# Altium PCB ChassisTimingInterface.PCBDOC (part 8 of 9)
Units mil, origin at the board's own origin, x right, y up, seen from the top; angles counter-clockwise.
Board outline 7007.87 x 4368.85 mil, 10 copper layers (Top Layer, Int1 (GND), Int2 (Sign), Int3 (Sign), Int4 (PWR), Int5 (GND), Int6 (Sign), Int7 (Sign), Int8 (GND), Bottom Layer), stack 54.89 mil thick; 537 components, 525 nets, 2288 pads, 1306 vias.
Unrouted connection lines stored in the file: 373.
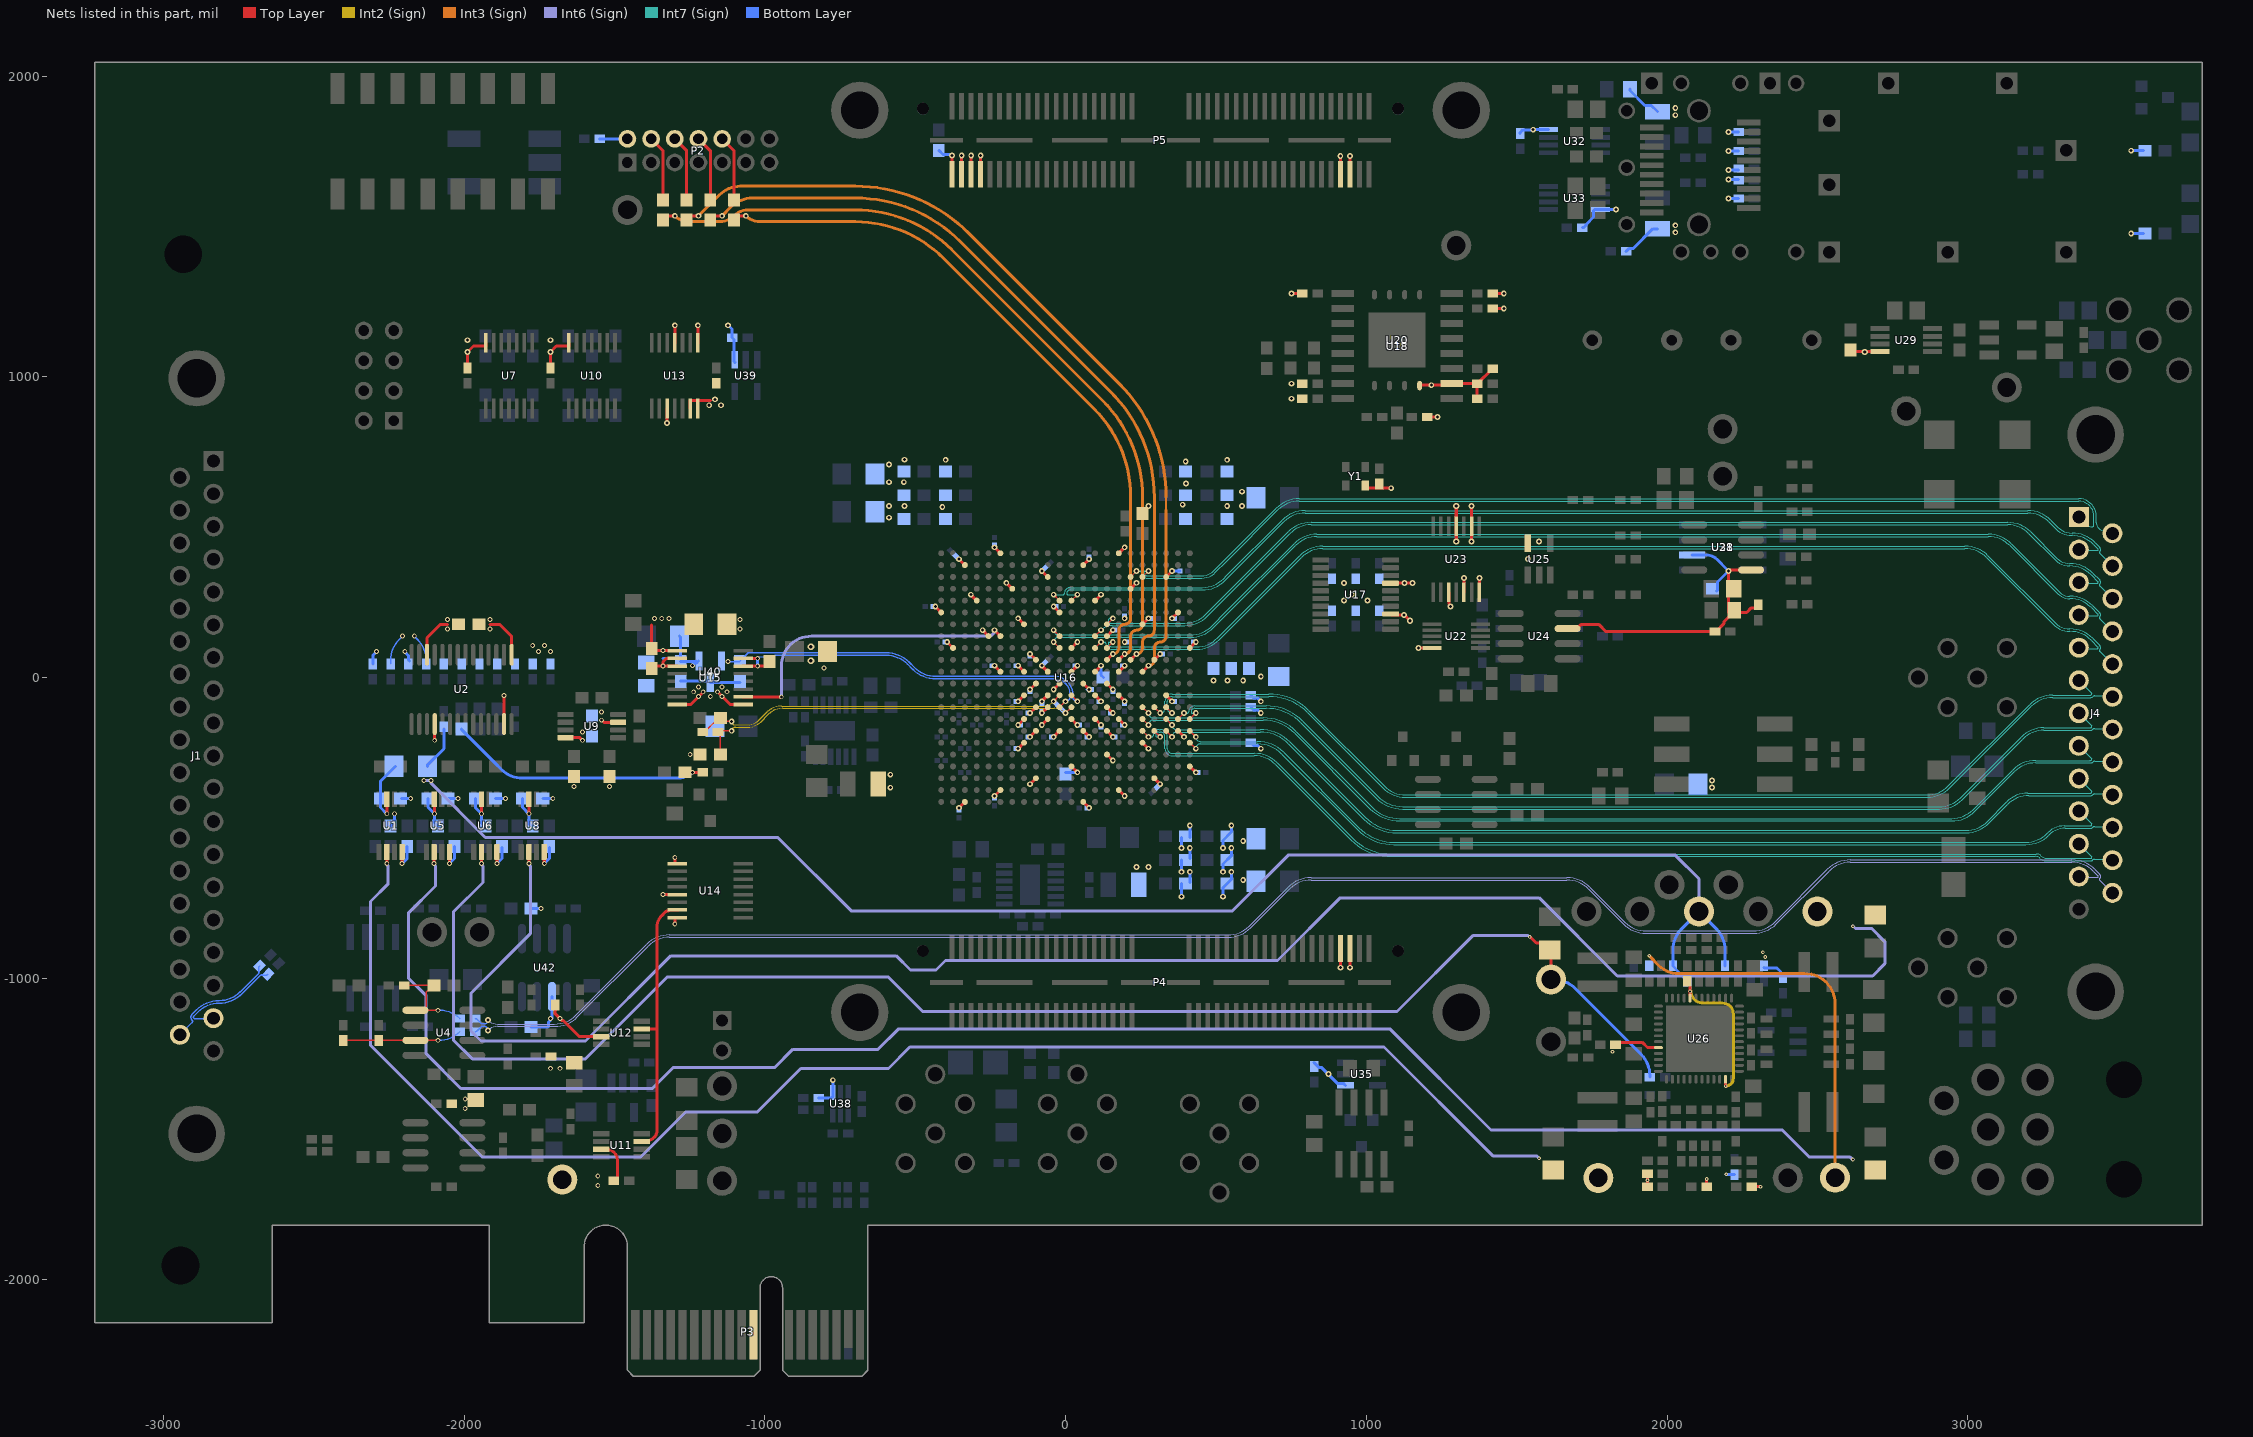
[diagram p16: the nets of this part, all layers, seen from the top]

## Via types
v1: diameter 19, hole 10, Top Layer to Bottom Layer, tented both sides, 667 vias
v2: diameter 20, hole 10, Top Layer to Bottom Layer, tented both sides, 248 vias
v3: diameter 16, hole 10, Top Layer to Bottom Layer, tented both sides, 191 vias
v4: diameter 12, hole 6, Top Layer to Bottom Layer, tented both sides, 85 vias
v5: diameter 19.68, hole 10, Top Layer to Bottom Layer, tented both sides, 50 vias
v6: diameter 17.72, hole 10, Top Layer to Bottom Layer, tented both sides, 19 vias
v7: diameter 19, hole 10, Top Layer to Bottom Layer, 15 vias
v8: diameter 23.62, hole 10, Top Layer to Bottom Layer, tented both sides, 14 vias
v9: diameter 20, hole 10, Top Layer to Bottom Layer, 11 vias
v10: diameter 16, hole 10, Top Layer to Bottom Layer, 3 vias
v11: diameter 22, hole 12, Top Layer to Bottom Layer, tented both sides, 2 vias
v12: diameter 19.02, hole 10, Top Layer to Bottom Layer, tented both sides, 1 vias

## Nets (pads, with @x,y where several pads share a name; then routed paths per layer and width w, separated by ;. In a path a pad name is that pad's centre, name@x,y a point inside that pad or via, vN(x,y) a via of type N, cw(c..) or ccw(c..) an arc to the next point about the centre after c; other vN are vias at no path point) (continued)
SQSPI.XMUX3: U15.10 U16.F15 | length 1033.6
  Top Layer w10: U15.10@-1071.85,-63.98 v3(-944.88,-63.98) ; v1(-236.22,157.48) U16.F15@-216.54,137.8
  Int6 (Sign) w10: v3(-944.88,-63.98) -944.88,37.8 cw(c-844.88,37.8) -844.88,137.8 -536.42,137.8 -255.91,137.8 ccw(c-255.91,157.48) v1(-236.22,157.48)
SYNC: U11.7 U12.7 U14.15 | length 900.2
  Top Layer w9.5: -1358.27,-1475.38 -1358.27,-1461.62 ; -1358.27,-1321.84 -1358.27,-1308.08
  Top Layer w10: U11.7@-1409.45,-1542.32 -1400.4,-1542.32 ccw(c-1400.4,-1496.21) -1381.66,-1538.34 ccw(c-1400.4,-1496.21) -1367.82,-1528.84 ; U12.7@-1409.45,-1168.31 -1358.27,-1168.31 ; -1367.79,-1528.82 ccw(c-1390.79,-1505.82) -1358.27,-1505.82 -1358.27,-1475.38 ; -1358.27,-1461.62 -1358.27,-1321.84 ; -1358.27,-1308.08 -1358.27,-1168.31 ; U14.15@-1290.35,-772.64 -1291.26,-773.54 -1317.83,-773.54 -1320.33,-776.04 -1323.25,-776.04 ccw(c-1323.25,-785.63) -1323.72,-776.05 ccw(c-1323.25,-785.63) -1330.02,-778.84 -1342.75,-791.57 ccw(c-1305.29,-829.03) -1358.27,-829.03 -1358.27,-1168.31
T1_11.T1_N: J4.14 U16.V20 | length 3444.8
  Top Layer w5: U16.V20@255.91,334.65 v1(275.59,354.33)
  Int7 (Sign) w3: v1(275.59,354.33) 263.84,354.33 ccw(c263.84,350.39) 259.91,350.39 ccw(c271.72,350.39) 271.72,338.58 452.76,338.58 ccw(c452.76,395.61) 493.08,355.29 536.42,398.62 700.85,563.05 cw(c777.05,486.85) 777.05,594.61 3369.29,594.61 cw(c3369.29,536.61) 3427.29,536.61 3427.29,515.43 ccw(c3454.68,515.43) 3435.31,496.06 ccw(c3454.68,515.43) 3454.68,488.04 3461.06,488.04 cw(c3461.06,459.71) J4.14@3481.1,479.74
T1_11.T1_P: J4.1 U16.U20 | length 3456.6
  Top Layer w5: U16.U20@216.54,334.65 v1(236.22,354.33)
  Int7 (Sign) w3: v1(236.22,354.33) 247.97,354.33 cw(c247.97,350.39) 251.91,350.39 ccw(c271.72,350.39) 271.72,330.58 452.86,330.58 ccw(c452.86,395.35) 498.66,349.55 536.42,387.31 706.43,557.32 cw(c777.14,486.61) 777.14,586.61 3369.29,586.61 cw(c3369.29,536.61) 3419.29,536.61 3419.29,533.3 3419.29,514.74 3419.29,505.33 ; J4.1@3369.29,534.09 3395.23,508.15 ccw(c3409.3,522.22) 3409.3,502.33 3416.29,502.33 ccw(c3416.29,505.33) 3418.42,503.21 ccw(c3416.29,505.33) 3419.29,505.33 ; 3419.29,514.69 3419.29,505.33
T1_11.T2_N: J4.15 U16.L18 | length 3736.8
  Top Layer w5: v1(-39.37,275.59) U16.L18@-19.69,255.91
  Int7 (Sign) w3: v1(-39.37,275.59) -7.94,275.59 ccw(c-7.94,279.53) -4,279.53 cw(c15.81,279.53) 15.81,299.34 454.77,299.34 ccw(c454.77,399.34) 525.48,328.63 536.42,339.57 720.53,523.68 cw(c796.73,447.48) 796.73,555.24 3199.33,555.24 cw(c3199.33,447.48) 3275.53,523.68 3298.95,500.26 ccw(c3346.8,548.11) 3346.8,480.44 cw(c3346.8,372.53) 3423.11,448.83 3438.59,433.35 cw(c3430.9,425.65) 3441.78,425.65 ; 3441.78,425.61 cw(c3430.78,425.61) 3438.56,417.83 ccw(c3440.68,415.71) 3437.68,415.71 ccw(c3440.68,415.71) 3438.56,413.58 J4.15@3481.1,371.04
T1_11.T2_P: J4.2 U16.M18 | length 3705.1
  Top Layer w5: U16.M18@19.69,255.91 v1(39.37,275.59)
  Int7 (Sign) w3: v1(39.37,275.59) 7.94,275.59 cw(c7.94,279.53) 4,279.53 cw(c15.81,279.53) 15.81,291.34 454.81,291.34 ccw(c454.81,399.24) 531.11,322.94 536.42,328.25 726.12,517.95 cw(c796.83,447.24) 796.83,547.24 3199.23,547.24 cw(c3199.23,447.24) 3269.94,517.95 3293.34,494.56 ccw(c3346.74,547.95) 3346.74,472.44 cw(c3346.77,372.44) 3417.48,443.15 3432.9,427.73 cw(c3430.78,425.61) 3433.78,425.61 cw(c3430.78,425.61) 3432.9,423.48 cw(c3430.78,425.61) 3430.78,422.61 3376.02,422.61 cw(c3376.02,432.13) J4.2@3369.29,425.39
T1_11.T3_N: J4.16 U16.R16 | length 3628.5
  Top Layer w5: U16.R16@137.8,177.17 v1(157.48,196.85)
  Int7 (Sign) w3: v1(157.48,196.85) 149.61,196.85 ccw(c149.61,188.98) 141.73,188.98 ccw(c149.54,188.98) 149.54,181.17 395.65,181.17 ccw(c395.65,281.17) 466.36,210.45 536.42,280.51 740.22,484.31 cw(c816.42,408.11) 816.42,515.87 3132.67,515.87 cw(c3132.67,408.11) 3208.86,484.31 3296.19,396.98 ccw(c3339.5,440.29) 3339.5,379.04 cw(c3339.5,271.13) 3415.81,347.44 3438.59,324.65 cw(c3430.9,316.95) 3441.78,316.95 ; 3441.78,316.9 cw(c3430.78,316.9) 3438.56,309.13 ccw(c3440.68,307) 3437.68,307 ccw(c3440.68,307) 3438.56,304.88 J4.16@3481.1,262.34
T1_11.T3_P: J4.3 U16.P15 | length 3612.5
  Top Layer w5: U16.P15@98.43,137.8 v1(118.11,157.48)
  Int7 (Sign) w3: v1(118.11,157.48) cw(c155.98,119.61) 155.98,173.17 395.69,173.17 ccw(c395.69,281.07) 471.99,204.77 536.42,269.2 745.8,478.58 cw(c816.51,407.87) 816.51,507.87 3132.57,507.87 cw(c3132.57,407.87) 3203.28,478.58 3290.58,391.28 ccw(c3339.43,440.13) 3339.43,371.04 cw(c3339.47,271.04) 3410.18,341.75 3432.9,319.03 cw(c3430.78,316.9) 3433.78,316.9 cw(c3430.78,316.9) 3432.9,314.78 cw(c3430.78,316.9) 3430.78,313.9 3376.02,313.9 cw(c3376.02,323.43) J4.3@3369.29,316.69
T1_11.T4_N: J4.17 U16.L15 | length 3823.1
  Top Layer w5: v1(-39.37,157.48) U16.L15@-19.69,137.8
  Int7 (Sign) w3: v1(-39.37,157.48) ccw(c-23.69,157.48) -23.69,141.8 415.34,141.8 ccw(c415.34,241.8) 486.05,171.09 536.42,221.46 759.9,444.94 cw(c836.1,368.74) 836.1,476.5 3068.68,476.5 cw(c3068.68,368.56) 3145.01,444.89 3305.45,284.45 ccw(c3339.5,318.5) 3339.5,270.34 cw(c3339.5,162.43) 3415.81,238.73 3438.59,215.95 cw(c3430.9,208.25) 3441.78,208.25 ; 3441.78,208.2 cw(c3430.78,208.2) 3438.56,200.43 ccw(c3440.68,198.3) 3437.68,198.3 ccw(c3440.68,198.3) 3438.56,196.18 J4.17@3481.1,153.64
T1_11.T4_P: J4.4 U16.L14 | length 3804
  Top Layer w5: v1(-39.37,118.11) U16.L14@-19.69,98.43
  Int7 (Sign) w3: v1(-39.37,118.11) cw(c-23.69,118.11) -23.69,133.8 415.38,133.8 ccw(c415.38,241.7) 491.67,165.4 536.42,210.14 765.49,439.21 cw(c836.2,368.5) 836.2,468.5 3068.66,468.5 cw(c3068.66,368.5) 3139.37,439.21 3299.82,278.76 ccw(c3339.46,318.4) 3339.46,262.34 cw(c3339.47,162.34) 3410.18,233.05 3432.9,210.32 cw(c3430.78,208.2) 3433.78,208.2 cw(c3430.78,208.2) 3432.9,206.08 cw(c3430.78,208.2) 3430.78,205.2 3376.02,205.2 cw(c3376.02,214.72) J4.4@3369.29,207.99
T1_11.T5_N: J4.18 U16.R14 | length 3685.5
  Top Layer w5: U16.R14@137.8,98.43 v1(157.48,118.11)
  Int7 (Sign) w3: v1(157.48,118.11) 145.73,118.11 ccw(c145.73,114.17) 141.8,114.17 ccw(c153.61,114.17) 153.61,102.36 434.96,102.36 ccw(c434.96,202.36) 505.67,131.65 536.42,162.4 779.59,405.57 cw(c855.79,329.37) 855.79,437.13 2990.75,437.13 cw(c2990.75,329.19) 3067.07,405.52 3290.76,181.83 ccw(c3339.5,230.57) 3339.5,161.64 cw(c3339.5,53.73) 3415.81,130.03 3438.59,107.25 cw(c3430.9,99.55) 3441.78,99.55 ; 3441.78,99.5 cw(c3430.78,99.5) 3438.56,91.72 ccw(c3440.68,89.6) 3437.68,89.6 ccw(c3440.68,89.6) 3438.56,87.48 J4.18@3481.1,44.94
T1_11.T5_P: J4.5 U16.P14 | length 3679
  Top Layer w5: U16.P14@98.43,98.43 v1(118.11,118.11)
  Int7 (Sign) w3: v1(118.11,118.11) 129.86,118.11 cw(c129.86,114.17) 133.8,114.17 ccw(c153.61,114.17) 153.61,94.36 435,94.36 ccw(c435,202.26) 511.29,125.97 536.42,151.09 785.17,399.84 cw(c855.88,329.13) 855.88,429.13 2990.72,429.13 cw(c2990.72,329.13) 3061.43,399.84 3285.13,176.14 ccw(c3339.46,230.47) 3339.46,153.64 cw(c3339.47,53.64) 3410.18,124.35 3432.9,101.62 cw(c3430.78,99.5) 3433.78,99.5 cw(c3430.78,99.5) 3432.9,97.38 cw(c3430.78,99.5) 3430.78,96.5 3376.02,96.5 cw(c3376.02,106.02) J4.5@3369.29,99.29
T1_11.T6_N: J4.19 U16.Y9 | length 3484.4
  Top Layer w5: U16.Y9@334.65,-98.43 v1(354.33,-118.11)
  Int7 (Sign) w3: v1(354.33,-118.11) cw(c354.33,-102.43) 338.65,-102.43 338.65,-78.68 cw(c354.33,-78.68) 354.33,-62.99 536.42,-62.99 676.45,-62.99 cw(c676.45,-242.99) 803.73,-115.71 1054.15,-366.13 ccw(c1130.51,-289.76) 1130.51,-397.76 2864.63,-397.76 ccw(c2864.63,-289.86) 2940.93,-366.16 3211.48,-95.6 cw(c3282.19,-166.31) 3282.19,-66.31 3409.25,-66.31 ccw(c3409.25,-57.19) 3415.7,-63.64 cw(c3422.15,-70.09) 3422.15,-60.97 3474.37,-60.97 cw(c3474.37,-70.49) J4.19@3481.1,-63.76
T1_11.T6_P: J4.6 U16.W9 | length 3491
  Top Layer w5: U16.W9@295.28,-98.43 v1(314.96,-118.11)
  Int7 (Sign) w3: v1(314.96,-118.11) ccw(c314.96,-102.43) 330.65,-102.43 330.65,-78.68 cw(c354.33,-78.68) 354.33,-54.99 536.42,-54.99 676.45,-54.99 cw(c676.45,-242.99) 809.39,-110.06 1059.8,-360.47 ccw(c1130.51,-289.76) 1130.51,-389.76 2864.59,-389.76 ccw(c2864.59,-289.76) 2935.3,-360.47 3205.86,-89.92 ; 3205.86,-89.92 cw(c3282.15,-166.21) 3282.15,-58.31 3406.71,-58.31 ccw(c3406.71,-51.07) 3411.83,-56.19 ccw(c3409.71,-54.07) 3412.71,-54.07 ccw(c3409.71,-54.07) 3411.83,-51.95 J4.6@3369.29,-9.41
T1_11.T7_N: J4.20 U16.AB8 | length 3344.3
  Top Layer w5: U16.AB8@413.39,-137.8 v1(433.07,-118.11)
  Int7 (Sign) w3: v1(433.07,-118.11) 421.32,-118.11 cw(c421.32,-114.17) 417.39,-114.17 cw(c429.2,-114.17) 429.2,-102.36 536.42,-102.36 666.77,-102.36 cw(c666.77,-266.36) 782.73,-150.4 1033.15,-400.81 ccw(c1120.83,-313.13) 1120.83,-437.13 2905.22,-437.13 ccw(c2905.22,-329.23) 2981.52,-405.53 3182.75,-204.3 cw(c3253.46,-275.01) 3253.46,-175.01 3409.25,-175.01 ccw(c3409.25,-165.89) 3415.7,-172.34 cw(c3422.15,-178.79) 3422.15,-169.67 3474.37,-169.67 cw(c3474.37,-179.19) J4.20@3481.1,-172.46
T1_11.T7_P: J4.7 U16.AA8 | length 3350.9
  Top Layer w5: U16.AA8@374.02,-137.8 v1(393.7,-118.11)
  Int7 (Sign) w3: v1(393.7,-118.11) 405.45,-118.11 ccw(c405.45,-114.17) 409.39,-114.17 cw(c429.2,-114.17) 429.2,-94.36 536.42,-94.36 666.77,-94.36 cw(c666.77,-266.36) 788.39,-144.74 1038.81,-395.16 ccw(c1120.83,-313.13) 1120.83,-429.13 2905.18,-429.13 ccw(c2905.18,-329.13) 2975.89,-399.84 3177.12,-198.62 cw(c3253.42,-274.92) 3253.42,-167.01 3406.71,-167.01 ccw(c3406.71,-159.77) 3411.83,-164.89 ccw(c3409.71,-162.77) 3412.71,-162.77 ccw(c3409.71,-162.77) 3411.83,-160.65 J4.7@3369.29,-118.11
T1_11.T8_N: J4.21 U16.V8 | length 3441.7
  Top Layer w5: U16.V8@255.91,-137.8 v1(275.59,-157.48)
  Int7 (Sign) w3: v1(275.59,-157.48) cw(c291.28,-157.48) 291.28,-141.8 536.42,-141.8 657.06,-141.8 cw(c657.06,-289.8) 761.71,-185.14 1012.13,-435.56 ccw(c1111.13,-336.57) 1111.13,-476.57 2946.99,-476.57 ccw(c2946.99,-368.67) 3023.28,-444.96 3155.24,-313.01 cw(c3225.95,-383.72) 3225.95,-283.72 3409.25,-283.72 ccw(c3409.25,-274.59) 3415.7,-281.04 cw(c3422.15,-287.49) 3422.15,-278.37 3474.37,-278.37 cw(c3474.37,-287.89) J4.21@3481.1,-281.16
T1_11.T8_P: J4.8 U16.V9 | length 3435.7
  Top Layer w5: U16.V9@255.91,-98.43 v1(275.59,-118.11)
  Int7 (Sign) w3: v1(275.59,-118.11) ccw(c291.28,-118.11) 291.28,-133.8 536.42,-133.8 657.06,-133.8 cw(c657.06,-289.8) 767.37,-179.49 1017.79,-429.91 ccw(c1111.13,-336.57) 1111.13,-468.57 2946.95,-468.57 ccw(c2946.95,-368.57) 3017.66,-439.28 3149.62,-307.32 cw(c3225.91,-383.62) 3225.91,-275.72 3406.71,-275.72 ccw(c3406.71,-268.47) 3411.83,-273.59 ccw(c3409.71,-271.47) 3412.71,-271.47 ccw(c3409.71,-271.47) 3411.83,-269.35 J4.8@3369.29,-226.81
T1_11.T9_N: J4.22 U16.Y7 | length 3334.2
  Top Layer w5: U16.Y7@334.65,-177.17 v1(354.33,-196.85)
  Int7 (Sign) w3: v1(354.33,-196.85) cw(c370.02,-196.85) 370.02,-181.17 536.42,-181.17 647.38,-181.17 cw(c647.38,-313.17) 740.72,-219.83 991.14,-470.25 ccw(c1101.45,-359.94) 1101.45,-515.94 2993.99,-515.94 ccw(c2993.99,-408.04) 3070.29,-484.33 3132.92,-421.71 cw(c3203.63,-492.42) 3203.63,-392.42 3409.25,-392.42 ccw(c3409.25,-383.3) 3415.7,-389.74 cw(c3422.15,-396.19) 3422.15,-387.07 3474.37,-387.07 cw(c3474.37,-396.6) J4.22@3481.1,-389.86
T1_11.T9_P: J4.9 U16.Y8 | length 3328.6
  Top Layer w5: U16.Y8@334.65,-137.8 v1(354.33,-157.48)
  Int7 (Sign) w3: v1(354.33,-157.48) ccw(c370.02,-157.48) 370.02,-173.17 536.42,-173.17 647.38,-173.17 cw(c647.38,-313.17) 746.38,-214.17 996.8,-464.59 ccw(c1101.45,-359.94) 1101.45,-507.94 2993.95,-507.94 ccw(c2993.95,-407.94) 3064.66,-478.65 3129.92,-413.39 cw(c3199.86,-483.32) 3199.86,-384.42 3406.71,-384.42 ccw(c3406.71,-377.17) 3411.83,-382.3 ccw(c3409.71,-380.17) 3412.71,-380.17 ccw(c3409.71,-380.17) 3411.83,-378.05 J4.9@3369.29,-335.51
T1_11.T10_N: J4.23 U16.AB6 | length 3227.8
  Top Layer w5: U16.AB6@413.39,-216.54 v1(433.07,-236.22)
  Int7 (Sign) w3: v1(433.07,-236.22) cw(c448.76,-236.22) 448.76,-220.54 536.42,-220.54 637.7,-220.54 cw(c637.7,-336.54) 719.73,-254.51 970.14,-504.93 ccw(c1091.77,-383.31) 1091.77,-555.31 3193.58,-555.31 ccw(c3193.58,-447.41) 3269.87,-523.7 cw(c3324.4,-578.23) 3324.4,-501.12 3409.25,-501.12 ccw(c3409.25,-492) 3415.7,-498.45 cw(c3422.15,-504.9) 3422.15,-495.77 3474.37,-495.77 cw(c3474.37,-505.3) J4.23@3481.1,-498.56
T1_11.T10_P: J4.10 U16.AB7 | length 3222.1
  Top Layer w5: U16.AB7@413.39,-177.17 v1(433.07,-196.85)
  Int7 (Sign) w3: v1(433.07,-196.85) ccw(c448.76,-196.85) 448.76,-212.54 536.42,-212.54 637.7,-212.54 cw(c637.7,-336.54) 725.38,-248.86 975.8,-499.27 ccw(c1091.77,-383.31) 1091.77,-547.31 3193.53,-547.31 ccw(c3193.53,-447.31) 3264.24,-518.02 3266.33,-515.94 cw(c3321.42,-571.03) 3321.42,-493.12 3406.71,-493.12 ccw(c3406.71,-485.87) 3411.83,-491 ccw(c3409.71,-488.87) 3412.71,-488.87 ccw(c3409.71,-488.87) 3411.83,-486.75 J4.10@3369.29,-444.21
T1_11.T11_N: J4.24 U16.W7 | length 3428.1
  Top Layer w5: U16.W7@295.28,-177.17 v1(314.96,-196.85)
  Int7 (Sign) w3: v1(314.96,-196.85) 303.21,-196.85 cw(c303.21,-192.91) 299.28,-192.91 cw(c311.09,-192.91) 311.09,-181.1 314.96,-181.1 cw(c314.96,-196.85) 330.71,-196.85 330.71,-236.35 ccw(c354.33,-236.35) 354.33,-259.97 536.42,-259.97 628,-259.97 cw(c628,-359.97) 698.71,-289.26 949.12,-539.68 ccw(c1082.06,-406.74) 1082.06,-594.74 3224.9,-594.74 cw(c3224.9,-618.36) 3241.6,-601.66 ccw(c3258.3,-584.96) 3258.3,-608.58 3411.37,-608.58 ccw(c3411.37,-601.58) 3416.32,-606.53 cw(c3421.27,-611.47) 3421.27,-604.47 3474.37,-604.47 cw(c3474.37,-614) J4.24@3481.1,-607.26
T1_11.T11_P: J4.11 U16.V7 | length 3434.7
  Top Layer w5: U16.V7@255.91,-177.17 v1(275.59,-196.85)
  Int7 (Sign) w3: v1(275.59,-196.85) 287.34,-196.85 ccw(c287.34,-192.91) 291.28,-192.91 cw(c311.09,-192.91) 311.09,-173.1 314.96,-173.1 cw(c314.96,-196.85) 338.71,-196.85 338.71,-236.35 ccw(c354.33,-236.35) 354.33,-251.97 536.42,-251.97 628,-251.97 cw(c628,-359.97) 704.36,-283.6 954.78,-534.02 ccw(c1082.06,-406.74) 1082.06,-586.74 3228.21,-586.74 cw(c3228.21,-610.36) 3244.91,-593.66 ccw(c3261.61,-576.96) 3261.61,-600.58 3409.71,-600.58 ccw(c3409.71,-597.58) 3411.83,-599.7 ccw(c3409.71,-597.58) 3412.71,-597.58 ccw(c3409.71,-597.58) 3411.83,-595.45 J4.11@3369.29,-552.91
TCK_FPGA: R22.2 U16.V12 | length 2769.5
  Top Layer w10: R22.2@-1259.84,1529.53 -1253.94,1535.43 v1(-1220.47,1535.43) ; U16.V12@255.91,19.69 v1(275.59,39.37)
  Int3 (Sign) w6.5: 334.65,557.93 334.65,600.32
  Int3 (Sign) w10: v1(-1220.47,1535.43) -1151.34,1604.57 cw(c-1080.63,1533.86) -1080.77,1633.86 cw(c-1080.63,1533.86) -1080.63,1633.86 ; -1082.68,1633.86 -698.89,1633.86 cw(c-698.89,1100.81) -321.97,1477.73 178.52,977.24 cw(c-198.4,600.32) 334.65,600.32 ; v1(275.59,39.37) ccw(c275.59,59.06) 295.28,59.06 295.28,98.43 cw(c314.96,98.43) 314.96,118.11 ccw(c314.96,137.8) 334.65,137.8 334.65,517.96 334.65,557.93
TCK_JTAG: P2.6 R22.1 | length 226.9
  Top Layer w10: P2.6@-1299.21,1791.34 -1259.84,1751.97 R22.1@-1259.84,1580.71
TDI_FPGA: R27.2 U16.R13 | length 2353.9
  Top Layer w10: R27.2@-1102.36,1529.53 -1096.46,1535.43 v1(-1062.99,1535.43) ; U16.R13@137.8,59.06 v1(157.48,78.74)
  Int3 (Sign) w10: v1(-1062.99,1535.43) ccw(c-1015.47,1582.96) -1015.47,1515.75 -698.89,1515.75 cw(c-698.89,1100.8) -405.48,1394.21 95,893.73 cw(c-198.41,600.32) 216.54,600.32 216.54,517.96 216.54,196.85 cw(c196.85,196.85) 196.85,177.17 ccw(c196.85,157.48) 177.17,157.48 177.17,98.43 cw(c157.48,98.43) v1(157.48,78.74)
TDI_JTAG: P2.10 R27.1 | length 226.9
  Top Layer w10: P2.10@-1141.73,1791.34 -1102.36,1751.97 R27.1@-1102.36,1580.71
TDO_FPGA: R26.2 U16.U13 | length 2571.2
  Top Layer w10: R26.2@-1181.1,1529.53 -1175.2,1535.43 v1(-1141.73,1535.43) ; U16.U13@216.54,59.06 v1(236.22,78.74)
  Int3 (Sign) w10: v1(-1141.73,1535.43) -1111.97,1565.2 cw(c-1041.26,1494.49) -1041.4,1594.49 cw(c-1041.26,1494.49) -1041.26,1594.49 -964.57,1594.49 -698.89,1594.49 cw(c-698.89,1100.81) -349.81,1449.89 150.68,949.41 cw(c-198.41,600.32) 295.28,600.32 295.28,517.96 295.28,157.48 cw(c275.59,157.48) 275.59,137.8 ccw(c275.59,118.11) 255.91,118.11 255.91,98.43 cw(c236.22,98.43) v1(236.22,78.74)
TDO_JTAG: P2.8 R26.1 | length 226.9
  Top Layer w10: P2.8@-1220.47,1791.34 -1181.1,1751.97 R26.1@-1181.1,1580.71
TMS_FPGA: R20.2 U16.T13 | length 2662.5
  Top Layer w10: R20.2@-1338.58,1529.53 -1332.68,1535.43 v1(-1299.21,1535.43) ; U16.T13@177.17,59.06 v1(196.85,78.74)
  Int3 (Sign) w10: v1(-1299.21,1535.43) ccw(c-1251.69,1582.96) -1251.69,1515.75 -1149.89,1515.75 ccw(c-1149.89,1582.96) -1102.36,1535.43 cw(c-1054.84,1487.91) -1054.84,1555.12 -698.89,1555.12 cw(c-698.89,1100.81) -377.65,1422.05 122.84,921.57 cw(c-198.41,600.32) 255.91,600.32 255.91,517.96 255.91,177.17 cw(c236.22,177.17) 236.22,157.48 ccw(c236.22,137.8) 216.54,137.8 216.54,98.43 cw(c196.85,98.43) v1(196.85,78.74)
TMS_JTAG: P2.4 R20.1 | length 226.9
  Top Layer w10: P2.4@-1377.95,1791.34 -1338.58,1751.97 R20.1@-1338.58,1580.71
VCC: C6.1 C12.1 C23.1 C68.1 C87.2 C88.2 C90.2 C92.2 C94.2 C95.2 C96.2 C97.2 C98.2 C99.2 C100.2 C184.2 C200.2 FR1.1 FR3.2 L6.2 L7.2 P5.1 P5.3 P5.5 P5.7 R49.2 R103.2 R104.2 R108.2 R109.2 R111.2 R112.2 R169.1 TP12.1 U1.2 U7.14 U10.14 U13.1 U13.4 U13.10 U13.13 U13.14 U14.9 U14.13 U14.16 U17.13 U17.17 U23.2 U23.4 U23.10 U23.12 U23.14 U25.5 U29.8 U32.8 U33.8 U35.1 U39.1 | length 7577.4
  Top Layer w10: v3(-2256.89,-618.11) U1.2@-2256.89,-579.72 ; C6.1@-1988.19,1042.32 v1(-1988.19,1082.68) -1968.5,1102.36 -1928.07,1102.36 -1927.17,1103.27 U7.14@-1927.17,1113.19 ; -1712.6,1047.24 v1(-1712.6,1082.68) -1692.91,1102.36 -1652.48,1102.36 -1651.57,1103.27 U10.14@-1651.57,1113.19 ; v3(-1338.58,-721.46) U14.13@-1290.35,-721.46 ; v1(-1324.8,846.46) U13.10@-1324.8,894.69 ; v3(-1299.21,-818.9) U14.16@-1299.21,-799.21 ; U14.9@-1299.21,-618.11 v3(-1299.21,-598.43) ; U13.4@-1299.21,1113.19 v1(-1299.21,1171.5) ; U13.13@-1248.03,894.69 -1248.03,920.35 -1247.13,921.26 -1181.1,921.26 ; U13.1@-1222.44,1113.19 v1(-1222.44,1171.5) ; P5.1@-377.15,1673.83 v7(-377.15,1736.22) ; P5.3@-345.67,1673.83 v1@-345.67,1736.22 ; P5.5@-314.17,1673.83 v1@-314.17,1736.22 ; P5.7@-282.67,1673.83 v1@-282.67,1736.22 ; U17.13@1080.71,211.61 1083.66,208.66 v9(1125.98,208.66) v9(1145.67,188.98) ; U17.17@1080.71,313.98 1081.69,314.96 v9(1153.54,314.96) ; U23.10@1273.62,284.45 1274.53,283.54 1274.53,243.93 1279.53,238.93 v2(1279.53,236.22) ; v2(1299.21,452.76) v2(1299.21,570.87) ; U23.12@1324.8,284.45 v2(1324.8,330.77) ; v2(1350.39,452.76) v2(1350.39,570.87) ; U23.14@1375.98,284.45 v2(1375.98,330.77) ; C68.1@2598.43,1083.66 U29.8@2708.86,1083.66 ; v2(2657.48,1082.68) cw(c2659.86,1080.3) v2@2659.86,1083.66
  Int6 (Sign) w10: v3(-2256.89,-618.11) -2255.74,-619.26 -2255.74,-623.7 -2252.22,-627.22 -2252.22,-685.65 -2310.77,-744.2 -2310.77,-1222.95 -1939.49,-1594.24 -1412.78,-1594.24 -1263.68,-1445.13 -1025.58,-1445.13 -879.91,-1299.46 -588.57,-1299.46 -517.71,-1228.6 1058.95,-1228.6 1420.65,-1590.3 1566.14,-1590.3 1574.26,-1598.43 v4(1574.8,-1598.43)
  Bottom Layer w10: R169.1@-1777.56,-767.72 v3(-1744.09,-767.72) ; v1(-1122.05,1171.5) -1109.25,1158.7 -1109.25,1130.91 -1102.43,1124.08 -1102.43,1051.24 U39.1@-1098.43,1047.24 ; C184.2@-421.26,1753.15 -407.48,1739.37 -382.74,1739.37 -379.59,1736.22 v7(-377.15,1736.22) ; C100.2@826.77,-1280.51 843.5,-1297.24 852.36,-1297.24 905.59,-1350.47 925.28,-1350.47 U35.1@931.1,-1356.3 ; C92.2@1511.81,1809.06 1511.81,1812.49 1520.59,1821.27 1554.54,1821.27 v1(1555.12,1821.85) U32.8@1606.5,1821.85 ; C90.2@1718.31,1496.06 1722.24,1496.06 1731.02,1504.84 1731.02,1506.61 1755.91,1531.51 1755.91,1552.83 1759.18,1556.1 v1(1830.71,1556.1) ; C87.2@1864.17,1417.32 1872.95,1426.1 1886.73,1426.1 1952.76,1492.13 L6.2@1968.5,1492.13 ; C88.2@1876.97,1956.69 1876.97,1951.77 1926.26,1902.48 1947.91,1902.48 L7.2@1968.5,1881.89 ; v1(2204.72,1656.3) R111.2@2238.19,1656.3 ; v1(2204.72,1687.8) R112.2@2238.19,1687.8 ; R109.2@2322.83,-964.57 2323.9,-965.63 2365.24,-965.63 2377.05,-977.44 2377.05,-985.31 2377.95,-986.22 R108.2@2385.83,-986.22 ; v1(3543.31,1476.38) R103.2@3584.65,1476.38 ; v1(3543.31,1751.97) R104.2@3584.65,1751.97
  other v1: -1185.04,905.51 -1145.67,905.51 -1165.35,925.2 -1988.19,1122.05 -1712.6,1122.05 2027.56,1480.32 2027.56,1503.94 -345.21,1736.22 -313.72,1736.22 -282.22,1736.22 2027.56,1870.08 2027.56,1893.7
  other v2: 874.02,-1318.9 2149.61,-366.14 2149.61,-342.52 925.2,255.91 1003.94,255.91 952.76,275.59 925.2,314.96 1537.4,394.69 1574.8,452.76
  other v3: -1082.68,161.42 -1082.68,192.91
  other v4: 2326.77,-929.13 2318.9,-913.39
  other v9: 1127.36,314.96
VCC1V8: C101.2 C105.2 C106.2 C113.2 C130.2 C137.2 C146.2 C151.2 C161.2 L1.2 L8.2 R48.2 R124.2 TP10.1 U6.2 U16.H12 U16.K12 U16.M12 U16.P12 U16.R11 | length 5388.3
  Top Layer w10: U6.2@-1941.93,-579.72 -1941.86,-579.8 -1941.86,-618.02 v3(-1941.78,-618.09) ; v1(-157.48,39.37) U16.H12@-137.8,19.69 ; v1(-78.74,39.37) U16.K12@-59.06,19.69 ; U16.M12@19.69,19.69 v1(39.37,39.37) ; U16.P12@98.43,19.69 v1(118.11,39.37) ; U16.R11@137.8,-19.68 v1(157.48,-39.37) ; v4(1543.31,-862.2) 1543.85,-862.2 1544.85,-863.2 1546.28,-863.2 1565.66,-882.59 1587.31,-882.59 1614.17,-909.45 TP10.1@1614.17,-1003.94
  Int6 (Sign) w10: v3(-1941.78,-618.09) -1940.63,-619.24 -1940.63,-623.32 -1937.01,-626.95 -1937.01,-681.1 -2035.43,-779.53 -2035.43,-1204.72 -1972.44,-1267.72 -1595.84,-1267.72 -1323.08,-994.96 -590.3,-994.96 -475.03,-1110.24 1102.26,-1110.24 1354.23,-858.27 1537.96,-858.27 1540.89,-861.2 1541.77,-861.2 1542.77,-862.2 v4(1543.31,-862.2)
  Bottom Layer w10: v1(118.11,39.37) 118.11,7.87 C130.2@125.98,0 ; TP10.1@1614.17,-1003.94 1623.71,-1003.94 cw(c1623.71,-1103.94) 1694.43,-1033.23 1913.62,-1252.43 cw(c1842.91,-1323.14) 1942.91,-1323.14 R124.2@1942.91,-1328.74
  other v1: 236.22,-629.92 275.59,-629.92 -582.68,-366.14 -582.68,-322.83 492.13,-9.92 538.39,-9.92 590.55,-9.92 649.61,3.94
VCC2: C5.1 C19.2 C207.1 C210.1 C212.1 C214.1 FR1.2 R16.1 R168.1 R180.1 R192.1 R198.1 U2.1 U2.18 U5.7 U6.7 U8.7 U9.7 U15.1 | length 947.8
  Top Layer w10: U5.7@-2099.41,-404.53 -2098.92,-405.02 -2098.92,-452.26 v3(-2098.43,-452.76) ; v3(-2097.44,-208.66) U2.18@-2097.44,-154.53 ; U6.7@-1941.93,-404.53 -1941.64,-404.82 v3(-1941.64,-452.76) ; -1913.39,177.17 -1881.89,177.17 -1841.54,136.81 U2.1@-1841.54,75.79 ; v3(-1784.45,-452.76) U8.7@-1784.45,-404.53 ; v3(-1543.31,-141.73) -1542.16,-142.88 -1540.19,-142.88 -1534.45,-148.62 U9.7@-1487.2,-148.62 ; -1375.98,175.2 C19.2@-1375.98,97.44 -1369.09,90.55 v3(-1338.58,90.55) ; v3@-1338.58,89.57 U15.1@-1290.35,89.57
  Bottom Layer w10: R198.1@-2244.09,-494.09 -2231.3,-481.3 v3(-2231.3,-452.76) ; C214.1@-2120.08,-401.57 -2120.08,-431.1 v3(-2098.43,-452.76) -2098.43,-482.28 R192.1@-2086.61,-494.09 ; C212.1@-1962.6,-401.57 -1962.6,-431.79 v3(-1941.64,-452.76) -1941.64,-485.53 R180.1@-1929.13,-498.03 ; C210.1@-1805.12,-401.57 -1805.12,-432.09 v3(-1784.45,-452.76) -1784.45,-485.24 R168.1@-1771.65,-498.03
  other v3: -1633.86,-362.2 -1543.31,-114.17 -1913.92,161.42 -1913.92,192.91 -1366.14,196.85 -1342.52,196.85 -1318.9,196.85
VCCINT: C102.2 C103.2 C107.2 C108.2 C109.2 C117.2 C118.2 C119.2 C131.1 C133.1 C135.1 C138.1 C139.1 C140.1 C141.2 C144.1 C145.1 C153.1 C155.2 C157.1 C158.1 C159.1 C162.1 R96.2 R126.2 TP22.1 U5.2 U16.H8 U16.H10 U16.J7 U16.J9 U16.J11 U16.K8 U16.L7 U16.L11 U16.M8 U16.N7 U16.N11 U16.P8 U16.P10 U16.R7 U16.R9 U16.T8 U16.T10 | length 8049.9
  Top Layer w10: v3(-2099.41,-618.11) U5.2@-2099.41,-579.72 ; v1(-157.48,-157.48) U16.H8@-137.8,-137.8 ; v1(-157.48,-78.74) U16.H10@-137.8,-59.06 ; v1(-118.11,-196.85) U16.J7@-98.43,-177.17 ; v1(-118.11,-118.11) U16.J9@-98.43,-98.43 ; v1(-118.11,-39.37) U16.J11@-98.43,-19.68 ; v1(-78.74,-157.48) U16.K8@-59.06,-137.8 ; v1(-39.37,-196.85) U16.L7@-19.69,-177.17 ; v1(-39.37,-39.37) U16.L11@-19.69,-19.68 ; U16.M8@19.69,-137.8 v1(39.37,-157.48) ; U16.N7@59.06,-177.17 v1(78.74,-196.85) ; U16.N11@59.06,-19.68 v1(78.74,-39.37) ; U16.P8@98.43,-137.8 v1(118.11,-157.48) ; U16.P10@98.43,-59.06 v1(118.11,-78.74) ; U16.R7@137.8,-177.17 v1(157.48,-196.85) ; U16.R9@137.8,-98.43 v1(157.48,-118.11) ; U16.T8@177.17,-137.8 v1(196.85,-157.48) ; U16.T10@177.17,-59.06 v1(196.85,-78.74)
  Int3 (Sign) w10: v4(1940.94,-925.2) 1973.49,-957.75 ccw(c2037.48,-893.76) 2037.48,-984.25 2459.06,-984.25 cw(c2459.06,-1084.25) 2559.06,-1084.25 TP22.1@2559.06,-1662.89
  Int6 (Sign) w10: v3(-2099.41,-618.11) -2098.26,-619.26 -2098.26,-623.19 -2094.49,-626.97 -2094.49,-692.91 -2185.04,-783.46 -2185.04,-998.65 -2125.98,-1057.7 -2125.98,-1250.62 -2010.46,-1366.14 -1374.02,-1366.14 -1304.98,-1297.11 -967.75,-1297.11 -906.86,-1236.22 -623.4,-1236.22 -554.89,-1167.72 1078.52,-1167.72 1414.74,-1503.94 2383.24,-1503.94 2473.79,-1594.49 2609.15,-1594.49 2616.03,-1601.36 2616.57,-1601.36 2617.57,-1602.36 v4(2618.11,-1602.36)
  Bottom Layer w10: C159.1@-121.91,-117.97 C159.1@-118.11,-114.17 ; v1@72.05,-39.37 72.83,-39.37 C141.2@78.6,-45.14 ; v1(385.83,-728.35) C117.2@385.83,-685.04 ; v1(385.83,-645.67) C118.2@385.83,-606.3 ; v1(385.83,-566.93) C119.2@385.83,-531.5 ; C117.2@413.39,-681.1 v1(413.39,-645.67) ; C118.2@413.39,-602.36 v1(413.39,-566.93) ; C119.2@413.39,-531.5 v1(413.39,-492.13) ; v1(523.62,-728.35) 523.62,-698.82 551.18,-671.26 v1(551.18,-645.67) ; v1(523.62,-645.67) 523.62,-620.08 551.18,-592.52 v1(551.18,-566.93) ; v1(523.62,-566.93) 523.62,-541.34 551.18,-513.78 v1(551.18,-492.13)
  other v1: 590.55,-673.23 590.55,-543.31
VDD: C31.2 C32.2 C40.2 C104.2 C110.2 C111.2 C112.2 C114.2 C115.2 C116.2 C120.2 C121.2 C122.2 C123.2 C124.2 C125.2 C126.2 C127.2 C128.2 C132.2 C134.2 C136.2 C142.2 C143.2 C147.2 C149.2 C152.2 C156.2 C160.2 C164.2 C165.2 C167.2 C170.2 C171.2 C172.2 C177.2 C179.2 C183.2 C185.2 C186.2 C187.2 C188.2 C190.2 C191.2 C196.1 FR2.2 P2.2 P4.74 P4.76 P5.73 P5.75 R21.1 R25.2 R29.2 R32.2 R33.2 R34.1 R38.1 R40.2 R42.1 R43.2 R44.2 R61.2 R62.1 R72.2 R83.1 R97.2 R110.2 R113.2 R114.2 R117.1 R131.2 R134.2 R135.2 R157.2 R187.1 TP21.1 U8.2 U16.A17 U16.AA7 U16.AA17 U16.AB4 U16.AB14 U16.B14 U16.C1 U16.C21 U16.D18 U16.E15 U16.F2 U16.F12 U16.F22 U16.G19 U16.H6 U16.H16 U16.J3 U16.J13 U16.K20 U16.L17 U16.M4 U16.M14 U16.N1 U16.N21 U16.P18 U16.R5 U16.R15 U16.T2 U16.T12 U16.T22 U16.U19 U16.V6 U16.V16 U16.W3 U16.W13 U16.Y10 U16.Y20 U18.2 U20.8 U22.10 U26.8 U38.1 Y1.4 | length 9495.5
  Top Layer w10: v3@-1784.45,-617.13 U8.2@-1784.45,-579.72 ; R21.1@-1273.62,-314.96 v3(-1240.16,-314.96) -1204.72,-314.96 cw(c-1204.72,-318.9) R25.2@-1200.79,-318.9 ; v1(-433.07,236.22) U16.A17@-413.39,216.54 ; v1(-393.7,118.11) U16.B14@-374.02,98.43 ; v1(-354.33,-433.07) U16.C1@-334.65,-413.39 ; v1(-354.33,393.7) U16.C21@-334.65,374.02 ; v1(-314.96,275.59) U16.D18@-295.28,255.91 ; v1(-275.59,157.48) U16.E15@-255.91,137.8 ; v1(-236.22,-393.7) U16.F2@-216.54,-374.02 ; v1(-236.22,39.37) U16.F12@-216.54,19.69 ; v1(-236.22,433.07) U16.F22@-216.54,413.39 ; v1(-196.85,314.96) U16.G19@-177.17,295.28 ; v1(-157.48,-236.22) U16.H6@-137.8,-216.54 ; v1(-157.48,196.85) U16.H16@-137.8,177.17 ; v1(-118.11,-354.33) U16.J3@-98.43,-334.65 ; v1(-118.11,78.74) U16.J13@-98.43,59.06 ; v1(-78.74,354.33) U16.K20@-59.06,334.65 ; v1(-39.37,236.22) U16.L17@-19.69,216.54 ; U16.M4@19.69,-295.28 v1(39.37,-314.96) ; U16.M14@19.69,98.43 v1(39.37,118.11) ; U16.N1@59.06,-413.39 v1(78.74,-433.07) ; U16.N21@59.06,374.02 v1(78.74,393.7) ; U16.P18@98.43,255.91 v1(118.11,275.59) ; U16.R5@137.8,-255.91 v1(157.48,-275.59) ; U16.R15@137.8,137.8 v1(157.48,157.48) ; U16.T2@177.17,-374.02 v1(196.85,-393.7) ; U16.T12@177.17,19.69 v1(196.85,39.37) ; U16.T22@177.17,413.39 v1(196.85,433.07) ; U16.U19@216.54,295.28 v1(236.22,314.96) ; U16.V6@255.91,-216.54 v1(275.59,-236.22) ; U16.V16@255.91,177.17 v1(275.59,196.85) ; R29.2@255.91,545.28 255.91,547.24 273.87,565.21 273.87,569.14 v1(275.59,570.87) ; U16.W3@295.28,-334.65 v1(314.96,-354.33) ; U16.W13@295.28,59.06 v1(314.96,78.74) ; U16.Y10@334.65,-59.06 v1(354.33,-78.74) ; U16.Y20@334.65,334.65 v1(354.33,354.33) ; v1(354.33,196.85) U16.AA17@374.02,216.54 ; U16.AA7@374.02,-177.17 v1(393.7,-196.85) ; U16.AB4@413.39,-295.28 v1(433.07,-314.96) ; U16.AB14@413.39,98.43 v1(433.07,118.11) ; v1(751.39,1277.36) R33.2@787.4,1277.36 ; v1(913.77,1734.28) cw(c912.81,1733.32) 914.16,1733.32 P5.73@914.16,1673.83 ; v1(914.16,-964.57) P4.74@914.16,-900.6 ; v1(945.66,-964.57) P4.76@945.66,-900.6 ; P5.75@945.66,1673.83 v1(945.66,1734.28) ; Y1.4@1000,633.86 1003.94,629.92 v1(1082.68,629.92) ; v2(1173.23,98.43) U22.10@1218.5,98.43 ; U20.8@1180.02,972.44 U18.2@1259.84,972.44 ; R40.2@1202.95,866.14 v1(1236.99,866.14) ; U18.2@1283.46,977.36 C31.2@1368.89,977.36 ; C32.2@1368.9,927.36 C31.2@1368.9,977.35 ; R43.2@1420.07,1027.36 C31.2@1368.89,977.36 ; R42.1@1420.07,1227.36 v1(1457.48,1227.36) ; R44.2@1420.07,1277.36 v1(1457.48,1277.36) ; C40.2@1828.74,-1220.47 1836.61,-1212.6 1917.22,-1212.6 1934.92,-1230.3 U26.8@1961.69,-1230.3 ; R62.1@1933.19,-1653.54 1935.04,-1655.39 R61.2@1935.04,-1692.91 ; R72.2@2131.89,-1692.91 v4(2131.89,-1667.32) ; R83.1@2281.5,-1692.91 v4(2311.02,-1692.91)
  Int6 (Sign) w10: v3(-1784.45,-618.09) -1783.3,-619.24 -1783.3,-623.18 -1779.53,-626.95 -1779.53,-851.74 -1976.38,-1048.59 -1976.38,-1175.81 -1943.53,-1208.66 -1595.84,-1208.66 -1312.37,-925.2 -562.99,-925.2 -515.75,-972.44 -430.48,-972.44 -398.99,-940.94 704.72,-940.94 913.39,-732.28 1574.8,-732.28 1834.65,-992.13 2683.69,-992.13 2724.41,-951.4 2724.41,-877.95 2681.1,-834.65 2627.07,-834.65 2620.19,-827.77 2619.65,-827.77 2618.65,-826.77 v4(2618.11,-826.77)
  Bottom Layer w10: R187.1@-2007.87,-171.26 -2007.87,-173.23 -1897.64,-283.46 -1875.75,-305.36 ccw(c-1805.04,-234.65) -1875.68,-305.42 ccw(c-1805.04,-234.65) -1805.04,-334.65 -1287.68,-334.65 ccw(c-1287.68,-267.44) -1240.23,-315.04 ccw(c-1287.68,-267.44) v3(-1240.16,-314.96) ; R157.2@-1549.21,1791.34 P2.2@-1456.69,1791.34 ; C196.1@-820.87,-1397.64 -777.48,-1397.64 -773.62,-1393.78 v6(-773.62,-1338.58) ; C147.2@0,-314.96 v1(39.37,-314.96) ; v1(354.33,354.33) C116.2@380.71,354.33 ; R131.2@616.14,-216.54 624.92,-225.31 634.15,-225.31 634.72,-225.88 639.25,-225.88 v1@649.59,-236.22 ; R134.2@616.14,-98.43 624.92,-107.2 634.15,-107.2 634.72,-107.77 639.25,-107.77 v1@649.59,-118.11 ; R135.2@616.14,-59.06 624.92,-67.83 634.15,-67.83 634.72,-68.4 639.25,-68.4 v1@649.59,-78.74 ; v4(2196.85,-1651.57) R117.1@2224.41,-1651.57 ; v1(2204.72,1593.31) R110.2@2238.19,1593.31 ; v1(2204.72,1750.79) R113.2@2238.19,1750.79 ; v1(2204.72,1813.78) R114.2@2238.19,1813.78
  other v1: 649.61,-236.22 649.61,-118.11 649.61,-78.74 196.85,118.11 196.85,196.85 -586.61,531.5 -586.61,570.87 -535.5,570.87 537.4,570.87 586.61,570.87 389.76,574.8 586.61,618.11 400.39,645.67 -537.4,649.61 399.61,718.5 -535.5,724.41 537.4,723.96 751.39,927.36 1216.54,972.44 751.39,977.36
  other v3: -803.15,31.5
  other v4: 1935.04,-1671.26 1818.9,-1244.09
  other v7: -409.45,566.93 -586.61,649.61 -586.61,708.66 -398.23,723.96
VREF2V5: C7.1 C13.1 C15.1 C17.1 C211.2 R9.1 R13.1 TP3.1 U11.3 U12.3 U42.6 | length 518
  Top Layer w10: C13.1@-1691.93,-1101.38 -1696.85,-1101.38 -1696.85,-1118.11 -1674.29,-1140.67 -1669.5,-1140.67 -1616.27,-1193.9 U12.3@-1543.31,-1193.9 ; U11.3@-1543.31,-1567.91 -1529.45,-1567.91 cw(c-1529.45,-1610.02) -1513.73,-1570.96 cw(c-1529.45,-1610.02) -1499.7,-1580.23 cw(c-1522.1,-1602.66) -1490.4,-1602.66 -1490.4,-1664.45 -1499.18,-1673.23 C17.1@-1501.97,-1673.23
  Bottom Layer w10: C211.2@-1777.56,-1161.42 -1723.21,-1161.42 ccw(c-1723.21,-1154.91) -1718.61,-1159.51 -1718.61,-1145.19 -1707.28,-1133.86 U42.6@-1707.28,-1061.02
  other v3: -1555.12,-1688.98 -1555.12,-1657.48 -1996.06,-1433.07 -1996.06,-1401.57 -1712.6,-1299.21 -1681.1,-1299.21 -1712.6,-1133.86 -1681.1,-1133.86
VREF-PH: C55.2 C56.1 C63.2 C83.2 R79.2 U24.3 U28.5 U31.6 | length 1160.5
  Top Layer w10: U24.3@1669.29,162.8 1700.79,162.8 1715.16,177.17 1772.64,177.17 1796.26,153.54 2163.39,153.54 2188.98,179.13 2188.98,185.04 2223.43,219.49 C56.1@2223.43,224.41 ; C56.1@2204.78,216.54 R79.2@2204.78,312.93 ; R79.2@2222.44,295.28 R79.2@2204.78,312.93 ; C56.1@2223.43,216.54 2264.76,216.54 2280.4,232.17 2294.37,232.17 2303.15,240.95 C63.2@2303.15,243.62 ; U28.5@2279.53,358.07 2211.17,358.07 2207.49,354.39 v2(2204.72,354.33) R79.2@2204.78,312.93
  Bottom Layer w10: U31.6@2082.68,408.07 2129.92,408.07 cw(c2129.92,357.22) 2165.88,393.18 2201.46,357.6 v2@2204.05,357.6 ; C83.2@2165.35,287.4 2168.23,290.28 2168.23,317.83 v2(2204.72,354.33)
VREG: C53.1 FR6.1 R118.2 R121.2 R122.2 R190.1 TP15.1 U26.23 U26.44 | length 5820.5
  Top Layer w10: C53.1@2071.85,-1014.75 2075.71,-1018.61 2075.71,-1027.36 2076.77,-1028.42 v4(2076.77,-1043.3) U26.44@2076.77,-1056.18 ; U26.23@2194.96,-1345.39 2195.23,-1345.67 v4(2195.23,-1358.26)
  Int6 (Sign) w10: v3(-2133.86,-342.52) v3(-2110.24,-342.52) -2109.09,-343.67 -2109.09,-351.54 -1929.13,-531.5 -956.69,-531.5 -712.6,-775.59 555.12,-775.59 740.16,-590.55 2027.56,-590.55 2106.3,-669.29 TP15.1@2106.3,-777.56
  Int2 (Sign) w10: v4(2076.77,-1043.3) 2079.22,-1040.85 ccw(c2121.06,-1040.85) 2121.06,-1082.68 2185.04,-1082.68 cw(c2185.04,-1118.11) 2220.47,-1118.11 2220.47,-1333.02 cw(c2195.23,-1333.02) v4(2195.23,-1358.26)
  Bottom Layer w8: R122.2@2019.68,-958.66 R121.2@2066.93,-1009.84 R121.2@2075.71,-1018.62 ; R121.2@2076.71,-1018.62 2076.71,-1043.24 v4(2076.77,-1043.3)
  Bottom Layer w10: FR6.1@-2122.05,-295.28 -2122.05,-291.34 -2066.93,-236.22 R190.1@-2066.93,-171.26 ; R122.2@2019.68,-958.66 2019.68,-905.59 cw(c2119.68,-905.59) 2048.97,-834.88 TP15.1@2106.3,-777.56 2163.62,-834.88 cw(c2092.91,-905.59) 2192.91,-905.59 R118.2@2192.91,-958.66
VREG2: C216.1 FR6.2 U1.7 | length 234.7
  Top Layer w10: v3(-2256.89,-452.76) U1.7@-2256.89,-404.53
  Bottom Layer w10: v3(-2256.89,-452.76) -2277.56,-432.09 -2277.56,-344.49 FR6.2@-2228.35,-295.28
WAKE#: P3.B11
X1_N: J1.37 R203.2 | length 382.7
  Bottom Layer w5: J1.37@-2944.88,-1187.65 -2904.23,-1146.99 ccw(c-2908.11,-1143.1) -2902.61,-1143.1 ccw(c-2908.11,-1143.1) -2904.23,-1139.21 ; -2904.25,-1139.18 cw(c-2894.35,-1129.28) -2908.36,-1129.28 -2908.36,-1129.22 cw(c-2894.31,-1129.22) -2904.24,-1119.29 -2890.76,-1105.8 cw(c-2814.17,-1182.39) -2814.17,-1074.08 ccw(c-2814.17,-974.86) -2744.01,-1045.02 -2684.19,-985.19 ccw(c-2690.37,-979.02) -2681.63,-979.02 ccw(c-2683.89,-979.02) -2682.3,-977.42 -2682.3,-965.76 cw(c-2672.79,-965.76) R203.2@-2679.51,-959.04
X1_P: J1.18 R202.2 | length 369.1
  Bottom Layer w5: J1.18@-2833.07,-1132.65 cw(c-2838.13,-1127.59) -2838.13,-1134.74 -2894.26,-1134.74 cw(c-2894.26,-1129.24) -2898.14,-1133.13 cw(c-2894.26,-1129.24) -2899.76,-1129.24 cw(c-2894.26,-1129.24) -2898.14,-1125.35 -2884.76,-1111.97 cw(c-2814.05,-1182.68) -2814.05,-1082.68 ccw(c-2814.05,-975.15) -2738.02,-1051.18 -2678.11,-991.28 cw(c-2671.93,-997.46) -2671.93,-988.72 cw(c-2671.93,-990.98) -2670.34,-989.38 -2658.67,-989.38 ccw(c-2658.67,-979.88) R202.2@-2651.95,-986.6
XADC.XADC_REF_N: U16.L9 W2.2 | length 1103.9
  Top Layer w5: U16.L9@-19.69,-98.43 v1(0,-78.74)
  Bottom Layer w5: W2.2@-972.79,67 -965.49,74.29 -965.49,74.59 -604.7,74.59 -604.4,74.29 -596.38,74.29 cw(c-596.38,-25.71) -525.67,45.01 -508.01,27.35 ccw(c-431.3,104.06) -431.3,-4.43 -36.55,-4.43 cw(c-36.55,-56.36) 15.39,-56.36 15.39,-63.35 cw(c0,-63.35) v1(0,-78.74)
XADC.XADC_REF_P: C201.1 R194.2 R199.2 U16.M10 U40.2 | length 1485.7
  Top Layer w5: U16.M10@19.69,-59.06 v1(39.37,-78.74)
  Bottom Layer w5: R199.2@-2244.09,45.28 -2244.09,57 cw(c-2144.09,57) -2214.81,127.71 v3(-2204.72,137.8) ; v3(-2165.35,137.8) -2155.27,127.71 cw(c-2225.98,57) -2125.98,57 R194.2@-2125.98,45.28 ; v3(-1122.05,53.15) C201.1@-1082.68,53.15 -1082.68,55.12 -1055.2,82.59 -597.44,82.59 -597.14,82.89 -596.29,82.89 cw(c-596.29,-25.49) -519.65,51.15 -501.96,33.46 ccw(c-431.25,104.17) -431.25,4.17 -36.55,4.17 cw(c-36.55,-56.36) 23.99,-56.36 23.99,-63.36 ccw(c39.37,-63.36) v1(39.37,-78.74)
XADC.XADC_V_N: C22.2 C148.2 R23.2 U16.M9 | length 1283.1
  Top Layer w5: C22.2@-1155.51,-181.1 -1151.57,-177.17 v1(-1110.24,-177.17) ; R23.2@-1147.64,-255.91 C22.2@-1147.64,-188.98 ; v1(0,-118.11) U16.M9@19.69,-98.43
  Int2 (Sign) w3: v1(-1110.24,-177.17) cw(c-1098.49,-177.17) -1098.49,-165.42 -1058.96,-165.42 ccw(c-1058.96,-99.26) -1012.18,-146.04 -988.19,-122.05 ; -988.15,-122.01 cw(c-940.97,-169.27) -940.97,-102.49 -536.42,-102.49 -37.72,-102.49 cw(c-37.72,-155.83) v1(0,-118.11)
XADC.XADC_V_P: C22.1 C148.1 R24.2 U16.L10 | length 1260.5
  Top Layer w5: C22.1@-1206.69,-181.1 -1195.41,-169.82 -1189.51,-169.82 -1170.73,-151.04 -1164.82,-151.04 R24.2@-1147.64,-133.86 -1135.83,-145.67 v1(-1110.24,-145.67) ; v1(-39.37,-78.74) U16.L10@-19.69,-59.06
  Int2 (Sign) w3: v1(-1110.24,-145.67) ccw(c-1098.49,-145.67) -1098.49,-157.42 -1059.06,-157.42 ccw(c-1059.06,-99.04) -1017.77,-140.32 -991.49,-114.04 cw(c-944.28,-161.27) -944.28,-94.49 -536.42,-94.49 -70.19,-94.49 ; -78.74,-94.49 -70.19,-94.49 ; v1(-39.37,-78.74) -44.46,-83.83 cw(c-70.19,-58.1) -70.19,-94.49
XADCGND: C5.2 C19.1 C24.1 C154.1 C201.2 C202.2 C204.2 C207.2 C210.2 C212.2 C214.2 C216.2 FR4.2 R18.2 R23.1 R163.2 R164.2 R167.2 R172.2 R175.2 R177.2 R183.2 R188.2 R189.2 R191.2 R196.2 R197.2 R201.2 U1.4 U2.12 U2.27 U5.4 U6.4 U8.4 U9.4 U15.2 U15.3 U15.8 U15.9 U15.14 U15.15 U16.K9 U40.3 W2.1 | length 1739
  Top Layer w10: v3@-2205.71,-620.88 U1.4@-2205.71,-579.72 ; U2.12@-2123.03,75.79 -2123.03,132.13 -2077.99,177.17 -2055.12,177.17 ; v3@-2048.24,-618.08 U5.4@-2048.23,-579.72 ; v3(-1890.75,-618.09) U6.4@-1890.75,-579.72 ; U2.27@-1867.13,-154.53 v3(-1867.13,-59.06) ; U8.4@-1733.27,-579.72 U8.4@-1733.27,-579.72 -1733.21,-618.04 v3(-1733.16,-618.09) ; U9.4@-1662.4,-199.8 -1615.16,-199.8 v3(-1606.3,-208.66) ; C19.1@-1375.98,30.51 -1368.11,38.39 v3(-1338.58,38.39) ; U15.8@-1290.35,-89.57 -1246.06,-89.57 -1220.47,-63.98 v3(-1220.47,-62.99) ; U15.3@-1290.35,38.39 v3(-1338.58,38.39) ; U15.2@-1290.35,63.98 -1291.26,63.07 -1322.57,63.07 -1322.91,62.74 -1328.47,62.74 -1338.58,52.63 v3(-1338.58,38.39) ; -1231.61,-75.38 v3@-1206.02,-49.79 ; v3@-1158.27,-46.43 -1131.69,-73.01 ; v3(-1141.73,-62.99) -1115.16,-89.57 U15.9@-1071.85,-89.57 ; U15.14@-1071.85,38.39 -998.94,38.39 -984.25,53.07 C24.1@-984.25,53.26 ; U15.15@-1071.85,63.98 v3(-1023.62,63.98) ; v1(-78.74,-118.11) U16.K9@-59.06,-98.43
  Bottom Layer w3: v3(-1023.62,63.98) -1019.01,68.59 -994.38,68.59 W2.1@-992.79,67
  Bottom Layer w10: R201.2@-2303.15,45.28 -2303.03,45.4 -2303.03,73.79 -2291.34,85.48 v3(-2291.34,86.61) ; C216.2@-2208.66,-401.57 v3(-2177.17,-401.57) ; v3(-2205.71,-618.11) -2188.98,-601.38 R197.2@-2188.98,-561.02 ; v3(-2196.85,86.61) -2196.85,85.48 -2185.16,73.79 -2185.16,57.99 -2183.98,57.99 R196.2@-2181.1,55.12 ; C214.2@-2053.15,-401.57 v3(-2019.69,-401.57) ; v3@-2048.25,-618.09 -2031.5,-601.34 R189.2@-2031.5,-561.02 ; C212.2@-1895.67,-401.57 v3(-1862.2,-401.57) ; v3(-1890.75,-618.09) -1874.02,-601.36 R175.2@-1874.02,-564.96 ; C210.2@-1738.19,-401.57 v3(-1704.72,-401.57) ; v3(-1733.16,-618.09) -1716.54,-601.46 R164.2@-1716.54,-564.96 ; C202.2@-1279.53,-11.81 -1185.04,-11.81 U40.3@-1181.1,-15.75 C201.2@-1082.68,-15.75 ; v3(-1023.62,38.39) v3(-1023.62,63.98)
  other v3: -2048.25,-618.11 -1515.75,-362.2 -1248.03,-255.91 -1606.3,-181.1 -1181.1,-62.99 -1236.22,-47.24 -1204.72,-47.24 -1157.48,-47.24 -1125.98,-47.24 -1220.47,-31.5 -1141.73,-31.5 -1751.97,86.61 -1712.6,86.61 -1771.65,106.3 -1732.28,106.3 -2054.69,161.42 -2054.69,192.91
  other v11: -846.46,102.12
XADCVCC: C154.2 C202.1 C204.1 FR5.2 U16.K10 U40.1 | length 259.4
  Top Layer w10: v1(-78.74,-78.74) U16.K10@-59.06,-59.06
  Bottom Layer w10: -1338.58,62.99 -1279.53,62.99 -1279.53,133.86 FR5.2@-1283.46,137.8 ; C202.1@-1279.53,53.15 -1230.32,53.15 ; U40.1@-1228.35,55.12 -1230.32,53.15 ; U40.1@-1220.47,55.12 -1226.38,49.21 -1230.32,49.21 v3(-1240.16,39.37) -1240.16,43.31 U40.1@-1230.31,53.15
  other v11: -846.46,56.13
XOCTR_N: C3.2 R7.2 R185.1 U4.5 | length 338.6
  Top Layer w5: C3.2@-2192.91,-1023.62 -2106.3,-1023.62 -2104.33,-1025.59 -2119.55,-1040.81 -2121.52,-1040.81 -2125.92,-1045.21 -2125.92,-1093.82 -2126.36,-1094.26 -2126.36,-1098.31 U4.5@-2134.25,-1106.2 ; U4.5@-2161.42,-1106.1 -2134.35,-1106.1 U4.5@-2134.25,-1106.2 ; v3(-2086.62,-1106.3) -2086.72,-1106.2 U4.5@-2134.25,-1106.2
  Bottom Layer w5: v3(-2086.62,-1106.3) -2080.31,-1106.3 cw(c-2080.31,-1200.39) R185.1@-2013.78,-1133.86
XOCTR_P: C1.1 R4.2 R184.1 U4.7 | length 398.3
  Top Layer w5: C1.1@-2401.57,-1206.69 -2293.24,-1206.69 R4.2@-2283.46,-1216.47 ; R4.2@-2279.53,-1212.6 -2273.03,-1206.1 v3(-2086.62,-1206.1)
  Bottom Layer w5: v3(-2086.62,-1206.1) -2083.64,-1206.1 ccw(c-2083.64,-1107.31) R184.1@-2013.78,-1177.17
XOCTRL_N: J4.25 R185.2 | length 5852.6
  Int6 (Sign) w3: v2(-1919.87,-1139.1) ccw(c-1888.49,-1107.72) -1888.49,-1152.1 -1699.38,-1152.1 ccw(c-1699.38,-1052.1) -1628.67,-1122.81 -1393.11,-887.26 cw(c-1316.92,-963.45) -1316.92,-855.69 539.89,-855.69 ccw(c539.89,-755.69) 610.6,-826.4 740.18,-696.83 cw(c816.47,-773.13) 816.47,-665.23 1667.28,-665.23 cw(c1667.28,-773.14) 1743.58,-696.84 1859.98,-813.23 ccw(c1930.69,-742.52) 1930.69,-842.52 2287.32,-842.52 ccw(c2287.32,-742.52) 2358.03,-813.23 2533.48,-637.78 cw(c2609.78,-714.07) 2609.78,-606.17 3346.41,-606.17 cw(c3346.41,-714.09) 3422.72,-637.78 3438.59,-653.66 cw(c3430.9,-661.36) 3441.78,-661.36 ; 3441.78,-661.4 cw(c3430.78,-661.4) 3438.56,-669.18 ccw(c3440.68,-671.3) 3437.68,-671.3 ccw(c3440.68,-671.3) 3438.56,-673.42 J4.25@3481.1,-715.96
  Bottom Layer w5: R185.2@-1962.6,-1133.86 cw(c-1962.6,-1143.36) -1955.88,-1136.64 -1943.84,-1148.68 ccw(c-1937.01,-1141.85) -1937.01,-1151.51 -1932.28,-1151.51 ccw(c-1932.28,-1139.1) v2(-1919.87,-1139.1)
XOCTRL_P: J4.12 R184.2 | length 5834.1
  Int6 (Sign) w3: v2(-1919.87,-1173.1) cw(c-1888.49,-1204.49) -1888.49,-1160.1 -1699.34,-1160.1 ccw(c-1699.34,-1052.2) -1623.04,-1128.5 -1387.53,-892.98 cw(c-1316.82,-963.69) -1316.82,-863.69 539.93,-863.69 ccw(c539.93,-755.79) 616.23,-832.09 745.8,-702.52 cw(c816.51,-773.23) 816.51,-673.23 1667.24,-673.23 cw(c1667.24,-773.23) 1737.95,-702.52 1854.34,-818.9 ccw(c1930.66,-742.58) 1930.66,-850.52 2287.36,-850.52 ccw(c2287.36,-742.62) 2363.66,-818.92 2539.11,-643.46 cw(c2609.82,-714.17) 2609.82,-614.17 3346.37,-614.17 cw(c3346.37,-714.17) 3417.09,-643.46 3432.9,-659.28 cw(c3430.78,-661.4) 3433.78,-661.4 cw(c3430.78,-661.4) 3432.9,-663.52 cw(c3430.78,-661.4) 3430.78,-664.4 3376.02,-664.4 cw(c3376.02,-654.88) J4.12@3369.29,-661.61
  Bottom Layer w5: R184.2@-1962.6,-1177.17 ccw(c-1962.6,-1167.66) -1955.88,-1174.38 -1943.84,-1162.34 cw(c-1937.01,-1169.17) -1937.01,-1159.51 -1933.46,-1159.51 cw(c-1933.46,-1173.1) v2(-1919.87,-1173.1)
pads on no net: J1.38 J1.39 J2.7 J2.23 J2.24 J3.MH1 J3.MH2 J4.26 J4.27 P2.12 P2.14 P3.B12 P4.1 P4.2 P4.3 P4.4 P4.89 P4.90 P5.89 P5.90 S2.2 S2.4 U2.2 U2.3 U2.13 U3.1 U3.5 U3.8 U16.A6 U16.AA9 U16.AA10 U16.AA11 U16.AA13 U16.AA14 U16.AA15 U16.AA16 U16.AB10 U16.AB11 U16.AB12 U16.AB13 U16.AB15 U16.AB16 U16.AB17 U16.B6 U16.C5 U16.C7 U16.D5 U16.D7 U16.E10 U16.F10 U16.T14 U16.T15 U16.T16 U16.U15 U16.U16 U16.V10 U16.V13 U16.V14 U16.V15 U16.W10 U16.W11 U16.W12 U16.W14 U16.W15 U16.W16 U16.Y11 U16.Y12 U16.Y13 U16.Y14 U16.Y16 U16.Y17 U18.4 U18.5 U18.6 U18.11 U18.12 U18.13 U18.14 U19.1 U19.6 U20.9 U23.6 U23.8 U27.2 U29.1 U31.1 U31.3 U31.5 U31.7 U31.8 U32.1 U33.1 U33.4 U42.1 U42.3 U42.5 U42.7 U42.8
copper on no net:
  other v5: 1023.62,1043.31 1062.99,1043.31 1102.36,1043.31 1141.73,1043.31 1181.1,1043.31 1023.62,1082.68 1062.99,1082.68 1102.36,1082.68 1141.73,1082.68 1181.1,1082.68 1023.62,1122.05 1062.99,1122.05 1102.36,1122.05 1141.73,1122.05 1181.1,1122.05 1023.62,1161.42 1062.99,1161.42 1102.36,1161.42 1141.73,1161.42 1181.1,1161.42 1023.62,1200.79 1062.99,1200.79 1102.36,1200.79 1141.73,1200.79 1181.1,1200.79

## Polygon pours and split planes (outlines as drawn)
XADC.XADC_REF_P on Int3 (Sign) "XADC.XADC_REF_P_L04_P098" (solid, pour order 98): -2267.72,118.11 -1259.84,118.11 -1141.73,0 -1102.36,0 -1062.99,39.37 -1062.99,78.74 -1181.1,196.85 -2267.72,196.85
P12V on Int3 (Sign) "P12V_L04_P049" (solid, pour order 49): -2637.8,-1653.54 -2637.8,-1051.18 -2326.77,-740.16 -1641.73,-740.16 -1259.84,-1122.05 275.59,-1122.05 275.59,-1708.66 -1716.54,-1708.66 -1771.65,-1653.54
SFP_SH on Int3 (Sign) "S0" (solid, pour order 8): 3759.84,1358.27 1830.71,1358.27 1830.71,2027.56 3759.84,2027.56
no net on Int3 (Sign) "SHLD" (solid, pour order 4): -3228.35,2047.24 -3051.18,2047.24 -3051.18,-2145.67 -3228.35,-2145.67
NetC62_2 on Top Layer "NETC62_2_L01_P024" (solid, pour order 24): 2496.06,-1198.82 2303.15,-1198.82 2303.15,-1156.49 2265.81,-1156.49 2265.81,-1114.17 2342.48,-1114.17 2342.48,-875.91 2496.06,-875.91
AGND on Top Layer "AGND_L01_P097" (solid, pour order 97): 1561.02,11.75 1515.69,11.75 1397.64,-106.3 1561.02,-106.3
no net on Top Layer "NONET_L01_P083" (solid, pour order 83): -1031.5,-196.85
GND on Top Layer "SW_GND" (solid, pour order 13): 2629.92,-1161.42 2516.73,-1161.42 2516.73,-1210.63 2629.92,-1210.63 2629.92,-1259.84 2516.73,-1259.84 2516.73,-1311.03 2755.91,-1311.03 2755.91,-1110.25 2629.92,-1110.25
NetC61_2 on Top Layer "SW_PWR_2" (solid, pour order 22): 2496.06,-1545.26 2342.48,-1545.27 2342.48,-1306.77 2265.81,-1306.77 2265.81,-1264.75 2303.15,-1264.75 2303.15,-1222.64 2496.06,-1222.64
GND on Top Layer "GND_L01_P077" (solid, pour order 77): 1948.82,354.33 1968.5,374.02 1968.5,492.13 1948.82,511.81 1877.95,511.81 1877.95,354.33
VCC on Top Layer "VCC_L01_P071" (solid, pour order 71): 1523.7,476.5 1523.7,395.59 ccw(c1537.4,395.59) 1537.4,381.89 1574.8,381.89 ccw(c1574.8,393.7) 1586.61,393.7 1586.61,464.57 ccw(c1574.8,464.57) 1574.8,476.38 1523.62,476.38
no net on Top Layer "NONET_L01_P064" (solid, pour order 64): 2267.72,496.06
no net on Top Layer "NONET_L01_P063" (solid, pour order 63): 2259.84,496.06
P10V on Top Layer "P10V_L01_P055" (solid, pour order 55): 1594.49,74.8 1594.49,47.24 1527.56,47.24 1472.44,-7.87 1397.64,-7.87 1397.64,74.8
no net on Top Layer "NONET_L01_P056" (solid, pour order 56): 1464.57,0
VREF2V5 on Bottom Layer "VREF2V5_L10_P096" (solid, pour order 96): -1535.39,-1653.59 -1535.39,-1692.87 cw(c-1574.8,-1692.87) -1574.8,-1732.28 -1699.16,-1732.28 cw(c-1699.16,-1699.83) -1722.1,-1722.78 -1981.47,-1463.41 ccw(c-1997.69,-1479.63) -1997.69,-1456.69 -2007.87,-1456.69 cw(c-2007.87,-1437.01) -2027.56,-1437.01 -2027.56,-1397.64 cw(c-2007.87,-1397.64) -2007.87,-1377.95 -1981.95,-1377.95 cw(c-1981.94,-1410.39) -1959,-1387.46 -1739,-1607.45 ccw(c-1722.78,-1591.22) -1722.78,-1614.17 -1574.8,-1614.17 cw(c-1574.8,-1653.58)
no net on Bottom Layer "NONET_L10_P095" (solid, pour order 95): -2013.78,-1377.95
SENSE.SENS_120b_P on Bottom Layer "SENSE.SENS_120B_P_L10_P091" (solid, pour order 91): -275.59,-1409.56 -275.59,-1240.16 -192.91,-1240.16 -192.91,-1264.46 ccw(c-166.04,-1264.46) -185.04,-1283.46 ccw(c-166.03,-1264.45) -166.03,-1291.34 -98.43,-1291.34 -98.43,-1374.69 cw(c-144.32,-1374.69) -111.87,-1407.14 -132.23,-1427.5 cw(c-145.65,-1414.11) -145.67,-1433.07 -247.08,-1433.07 cw(c-247.08,-1392.78) -260.52,-1430.76 cw(c-252.98,-1409.45)
GND on Bottom Layer "GND_L10_P094" (solid, pour order 94): 811.02,-1326.77 795.28,-1342.52 795.28,-1425.2 858.27,-1425.2 858.27,-1342.52 842.52,-1326.77
GND on Bottom Layer "GND_L10_P093" (solid, pour order 93): 2366.14,-1125.99 2366.14,-1102.36 ccw(c2362.21,-1102.36) 2362.2,-1098.43 2343.48,-1098.43 cw(c2343.48,-1058.1) 2314.96,-1086.61 ccw(c2305.46,-1096.1) 2305.46,-1082.68 2303.15,-1082.68 ccw(c2303.15,-1098.42) 2287.4,-1098.43 2287.4,-1100.73 ccw(c2300.84,-1100.73) 2291.34,-1110.24 2294.8,-1113.7 ccw(c2333.97,-1074.52) 2333.97,-1129.92 2362.2,-1129.92 ccw(c2362.21,-1125.99)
